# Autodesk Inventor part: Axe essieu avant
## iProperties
Created: 2002-04
Part Number: Axe essieu avant
Material: Par défaut
Document SubType Name: Modélisation
Designer: Flavien MARTY
Control State: 0
Master: False
Checked Out: False
Shininess: 20.0
Length Units: 11269
Angle Units: 11279
Time Units: 11290
Mass Units: 11283
Length Display Precision: 3
Angle Display Precision: 2
Compacted: True
Density: 0.0
Volumn: 0.0
Area: 0.0
PropertySet Name: Model Information
Author: Flavien MARTY
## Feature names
1. Révolution1 [Revolution]
